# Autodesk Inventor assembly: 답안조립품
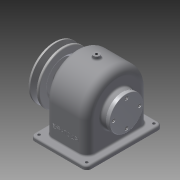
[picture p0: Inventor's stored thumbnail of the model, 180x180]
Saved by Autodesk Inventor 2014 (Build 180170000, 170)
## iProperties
Created: 2016-01
Part Number: 답안조립품
Document SubType Name: Assembly
Designer: L6
Author: L6
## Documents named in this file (16)
- C:\Users\L6\Desktop\답안조립품.iam
- C:\Users\L6\Desktop\본체.ipt
- C:\Users\L6\Desktop\460106V1001\베어링 6203.ipt
- C:\Users\L6\Desktop\460106V1001\축.ipt
- C:\Users\L6\Desktop\460106V1001\스퍼기어.ipt
- C:\Users\L6\Desktop\460106V1001\키 - 6 x 6 x 22.ipt
- C:\Users\L6\Desktop\460106V1001\부시1.ipt
- C:\Users\L6\Desktop\460106V1001\뒤커버.ipt
- C:\Users\L6\Desktop\460106V1001\볼트 M3 x 8.ipt
- C:\Users\L6\Desktop\460106V1001\앞커버.ipt
- C:\Users\L6\Desktop\460106V1001\볼트 M3 x 10.ipt
- C:\Users\L6\Desktop\460106V1001\오일씰 28 40 8.ipt
- C:\Users\L6\Desktop\460106V1001\V-벨트풀리.ipt
- C:\Users\L6\Desktop\460106V1001\키 - 5 x 5 x 18.ipt
- C:\Users\L6\Desktop\460106V1001\부시2.ipt
- C:\Users\L6\Desktop\460106V1001\멈춤나사 - M4x10.ipt
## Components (9 placed, 3 different names)
1. ISO 4762 M3 x 8:1
2. ISO 4762 M3 x 8:2
3. ISO 4762 M3 x 8:3
4. ISO 4762 M3 x 8:4
5. ISO 4762 M3 x 10:1
6. ISO 4762 M3 x 10:2
7. ISO 4762 M3 x 10:3
8. ISO 4762 M3 x 10:4
9. V-벨트풀리:1
